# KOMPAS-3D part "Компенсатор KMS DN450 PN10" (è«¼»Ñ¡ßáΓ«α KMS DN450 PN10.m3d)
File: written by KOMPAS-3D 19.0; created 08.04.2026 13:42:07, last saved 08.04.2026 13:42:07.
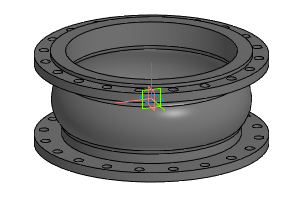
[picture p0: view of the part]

Document properties: Автор: Энергия; Полное имя файла: Z:\3.Личные\kachalov\3d для проектировщиков\7.1 Компенсатор\stp_Компенсатор KSM\Компенсатор KMS DN450 PN10.m3d

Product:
- Part/product: Компенсатор KMS DN450 PN10

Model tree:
1. Операция без истории:1  (labels: Компенсатор KMS DN450 PN10)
